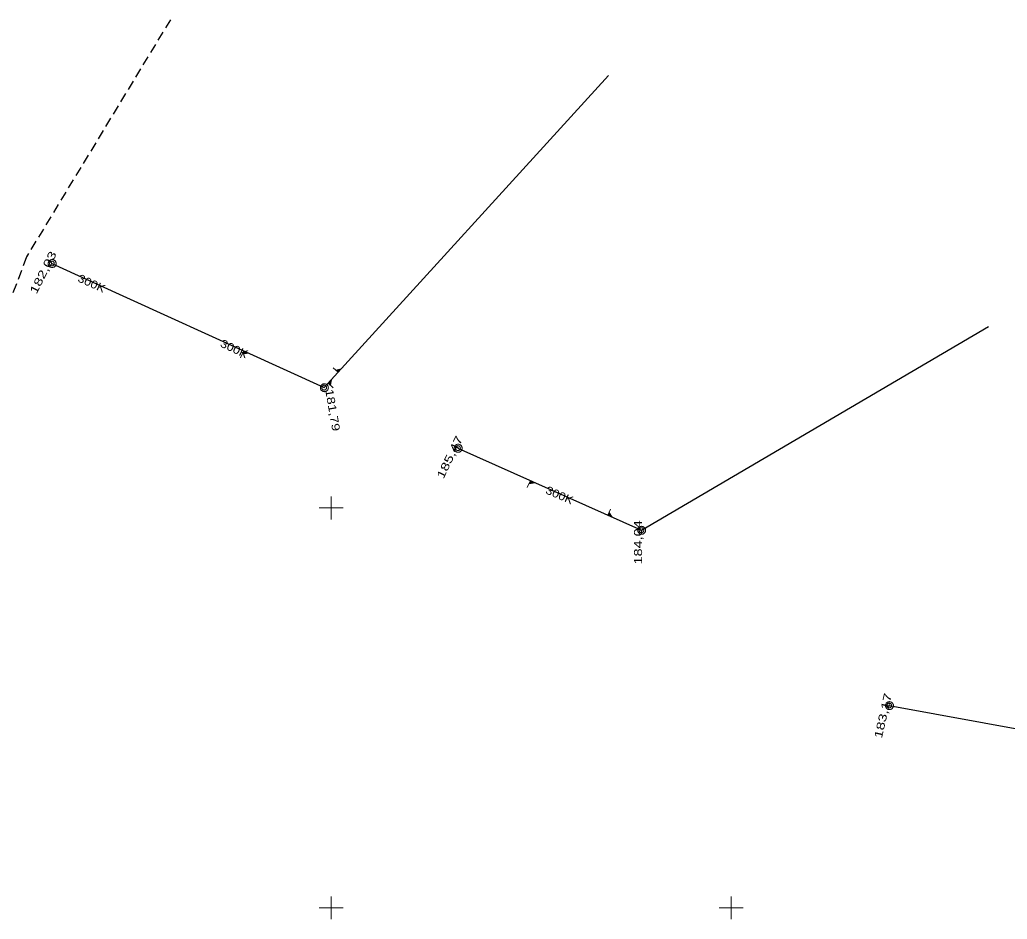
# Model space of a CAD drawing. Extents: x -740851 to -738888, y -1041382 to -1040235.
# Drawn here: x -740638.9 to -740515.5, y -1040351.4 to -1040239 of the extents above; entities that cross this region are included whole.
import ezdxf

# ---------------------------------------------------------------- set-up
doc = ezdxf.new("R2010")
doc.units = 0
doc.header["$LTSCALE"] = 0.4
doc.linetypes.add('MEDIUM_DASHED', pattern=[4.5, 3, -1.5])
for name, color, linetype, lineweight in [('1', 7, 'Continuous', 13), ('18', 7, 'Continuous', 13), ('19', 7, 'Continuous', 25), ('8', 7, 'Continuous', 13)]:
    doc.layers.add(name, color=color, linetype=linetype, lineweight=lineweight)

msp = doc.modelspace()

# ---------------------------------------------------------------- linework, layer by layer
at = {"layer": '1'}
for p, q in [((-740600, -1040298.571), (-740600, -1040301.429)), ((-740600, -1040298.571), (-740600, -1040301.429)), ((-740601.48, -1040300), (-740598.48, -1040300)), ((-740601.48, -1040300), (-740598.48, -1040300)), ((-740600, -1040348.571), (-740600, -1040351.429)), ((-740550, -1040348.571), (-740550, -1040351.429)), ((-740601.48, -1040350), (-740598.48, -1040350)), ((-740551.48, -1040350), (-740548.48, -1040350))]:
    msp.add_line(p, q, dxfattribs=at)
at = {"layer": '18'}
for points in [[(-740634.36, -1040269.45), (-740634.37, -1040269.4), (-740634.37, -1040269.35), (-740634.39, -1040269.3), (-740634.41, -1040269.25), (-740634.43, -1040269.2), (-740634.46, -1040269.16), (-740634.49, -1040269.12), (-740634.53, -1040269.08), (-740634.57, -1040269.05), (-740634.61, -1040269.02), (-740634.66, -1040269), (-740634.71, -1040268.98), (-740634.76, -1040268.96), (-740634.81, -1040268.96), (-740634.86, -1040268.95), (-740634.91, -1040268.96), (-740634.96, -1040268.96), (-740635.01, -1040268.98), (-740635.06, -1040269), (-740635.11, -1040269.02), (-740635.15, -1040269.05), (-740635.19, -1040269.08), (-740635.23, -1040269.12), (-740635.26, -1040269.16), (-740635.29, -1040269.2), (-740635.31, -1040269.25), (-740635.33, -1040269.3), (-740635.35, -1040269.35), (-740635.35, -1040269.4), (-740635.36, -1040269.45), (-740635.35, -1040269.5), (-740635.35, -1040269.55), (-740635.33, -1040269.6), (-740635.31, -1040269.65), (-740635.29, -1040269.7), (-740635.26, -1040269.74), (-740635.23, -1040269.78), (-740635.19, -1040269.82), (-740635.15, -1040269.85), (-740635.11, -1040269.88), (-740635.06, -1040269.9), (-740635.01, -1040269.92), (-740634.96, -1040269.94), (-740634.91, -1040269.94), (-740634.86, -1040269.95), (-740634.81, -1040269.94), (-740634.76, -1040269.94), (-740634.71, -1040269.92), (-740634.66, -1040269.9), (-740634.61, -1040269.88), (-740634.57, -1040269.85), (-740634.53, -1040269.82), (-740634.49, -1040269.78), (-740634.46, -1040269.74), (-740634.43, -1040269.7), (-740634.41, -1040269.65), (-740634.39, -1040269.6), (-740634.37, -1040269.55), (-740634.37, -1040269.5)], [(-740634.59, -1040269.44), (-740634.59, -1040269.41), (-740634.596, -1040269.38), (-740634.602, -1040269.35), (-740634.614, -1040269.32), (-740634.632, -1040269.29), (-740634.65, -1040269.266), (-740634.668, -1040269.242), (-740634.692, -1040269.218), (-740634.716, -1040269.2), (-740634.74, -1040269.182), (-740634.77, -1040269.164), (-740634.8, -1040269.152), (-740634.83, -1040269.146), (-740634.86, -1040269.14), (-740634.89, -1040269.14), (-740634.92, -1040269.14), (-740634.95, -1040269.146), (-740634.98, -1040269.152), (-740635.01, -1040269.164), (-740635.04, -1040269.182), (-740635.064, -1040269.2), (-740635.088, -1040269.218), (-740635.112, -1040269.242), (-740635.13, -1040269.266), (-740635.148, -1040269.29), (-740635.166, -1040269.32), (-740635.178, -1040269.35), (-740635.184, -1040269.38), (-740635.19, -1040269.41), (-740635.19, -1040269.44), (-740635.19, -1040269.47), (-740635.184, -1040269.5), (-740635.178, -1040269.53), (-740635.166, -1040269.56), (-740635.148, -1040269.59), (-740635.13, -1040269.614), (-740635.112, -1040269.638), (-740635.088, -1040269.662), (-740635.064, -1040269.68), (-740635.04, -1040269.698), (-740635.01, -1040269.716), (-740634.98, -1040269.728), (-740634.95, -1040269.734), (-740634.92, -1040269.74), (-740634.89, -1040269.74), (-740634.86, -1040269.74), (-740634.83, -1040269.734), (-740634.8, -1040269.728), (-740634.77, -1040269.716), (-740634.74, -1040269.698), (-740634.716, -1040269.68), (-740634.692, -1040269.662), (-740634.668, -1040269.638), (-740634.65, -1040269.614), (-740634.632, -1040269.59), (-740634.614, -1040269.56), (-740634.602, -1040269.53), (-740634.596, -1040269.5), (-740634.59, -1040269.47)], [(-740600.33, -1040284.97), (-740600.34, -1040284.92), (-740600.34, -1040284.87), (-740600.36, -1040284.82), (-740600.38, -1040284.77), (-740600.4, -1040284.72), (-740600.43, -1040284.68), (-740600.46, -1040284.64), (-740600.5, -1040284.6), (-740600.54, -1040284.57), (-740600.58, -1040284.54), (-740600.63, -1040284.52), (-740600.68, -1040284.5), (-740600.73, -1040284.48), (-740600.78, -1040284.48), (-740600.83, -1040284.47), (-740600.88, -1040284.48), (-740600.93, -1040284.48), (-740600.98, -1040284.5), (-740601.03, -1040284.52), (-740601.08, -1040284.54), (-740601.12, -1040284.57), (-740601.16, -1040284.6), (-740601.2, -1040284.64), (-740601.23, -1040284.68), (-740601.26, -1040284.72), (-740601.28, -1040284.77), (-740601.3, -1040284.82), (-740601.32, -1040284.87), (-740601.32, -1040284.92), (-740601.33, -1040284.97), (-740601.32, -1040285.02), (-740601.32, -1040285.07), (-740601.3, -1040285.12), (-740601.28, -1040285.17), (-740601.26, -1040285.22), (-740601.23, -1040285.26), (-740601.2, -1040285.3), (-740601.16, -1040285.34), (-740601.12, -1040285.37), (-740601.08, -1040285.4), (-740601.03, -1040285.42), (-740600.98, -1040285.44), (-740600.93, -1040285.46), (-740600.88, -1040285.46), (-740600.83, -1040285.47), (-740600.78, -1040285.46), (-740600.73, -1040285.46), (-740600.68, -1040285.44), (-740600.63, -1040285.42), (-740600.58, -1040285.4), (-740600.54, -1040285.37), (-740600.5, -1040285.34), (-740600.46, -1040285.3), (-740600.43, -1040285.26), (-740600.4, -1040285.22), (-740600.38, -1040285.17), (-740600.36, -1040285.12), (-740600.34, -1040285.07), (-740600.34, -1040285.02)], [(-740600.56, -1040284.96), (-740600.56, -1040284.93), (-740600.566, -1040284.9), (-740600.572, -1040284.87), (-740600.584, -1040284.84), (-740600.602, -1040284.81), (-740600.62, -1040284.786), (-740600.638, -1040284.762), (-740600.662, -1040284.738), (-740600.686, -1040284.72), (-740600.71, -1040284.702), (-740600.74, -1040284.684), (-740600.77, -1040284.672), (-740600.8, -1040284.666), (-740600.83, -1040284.66), (-740600.86, -1040284.66), (-740600.89, -1040284.66), (-740600.92, -1040284.666), (-740600.95, -1040284.672), (-740600.98, -1040284.684), (-740601.01, -1040284.702), (-740601.034, -1040284.72), (-740601.058, -1040284.738), (-740601.082, -1040284.762), (-740601.1, -1040284.786), (-740601.118, -1040284.81), (-740601.136, -1040284.84), (-740601.148, -1040284.87), (-740601.154, -1040284.9), (-740601.16, -1040284.93), (-740601.16, -1040284.96), (-740601.16, -1040284.99), (-740601.154, -1040285.02), (-740601.148, -1040285.05), (-740601.136, -1040285.08), (-740601.118, -1040285.11), (-740601.1, -1040285.134), (-740601.082, -1040285.158), (-740601.058, -1040285.182), (-740601.034, -1040285.2), (-740601.01, -1040285.218), (-740600.98, -1040285.236), (-740600.95, -1040285.248), (-740600.92, -1040285.254), (-740600.89, -1040285.26), (-740600.86, -1040285.26), (-740600.83, -1040285.26), (-740600.8, -1040285.254), (-740600.77, -1040285.248), (-740600.74, -1040285.236), (-740600.71, -1040285.218), (-740600.686, -1040285.2), (-740600.662, -1040285.182), (-740600.638, -1040285.158), (-740600.62, -1040285.134), (-740600.602, -1040285.11), (-740600.584, -1040285.08), (-740600.572, -1040285.05), (-740600.566, -1040285.02), (-740600.56, -1040284.99)], [(-740583.61, -1040292.54), (-740583.62, -1040292.49), (-740583.62, -1040292.44), (-740583.64, -1040292.39), (-740583.66, -1040292.34), (-740583.68, -1040292.29), (-740583.71, -1040292.25), (-740583.74, -1040292.21), (-740583.78, -1040292.17), (-740583.82, -1040292.14), (-740583.86, -1040292.11), (-740583.91, -1040292.09), (-740583.96, -1040292.07), (-740584.01, -1040292.05), (-740584.06, -1040292.05), (-740584.11, -1040292.04), (-740584.16, -1040292.05), (-740584.21, -1040292.05), (-740584.26, -1040292.07), (-740584.31, -1040292.09), (-740584.36, -1040292.11), (-740584.4, -1040292.14), (-740584.44, -1040292.17), (-740584.48, -1040292.21), (-740584.51, -1040292.25), (-740584.54, -1040292.29), (-740584.56, -1040292.34), (-740584.58, -1040292.39), (-740584.6, -1040292.44), (-740584.6, -1040292.49), (-740584.61, -1040292.54), (-740584.6, -1040292.59), (-740584.6, -1040292.64), (-740584.58, -1040292.69), (-740584.56, -1040292.74), (-740584.54, -1040292.79), (-740584.51, -1040292.83), (-740584.48, -1040292.87), (-740584.44, -1040292.91), (-740584.4, -1040292.94), (-740584.36, -1040292.97), (-740584.31, -1040292.99), (-740584.26, -1040293.01), (-740584.21, -1040293.03), (-740584.16, -1040293.03), (-740584.11, -1040293.04), (-740584.06, -1040293.03), (-740584.01, -1040293.03), (-740583.96, -1040293.01), (-740583.91, -1040292.99), (-740583.86, -1040292.97), (-740583.82, -1040292.94), (-740583.78, -1040292.91), (-740583.74, -1040292.87), (-740583.71, -1040292.83), (-740583.68, -1040292.79), (-740583.66, -1040292.74), (-740583.64, -1040292.69), (-740583.62, -1040292.64), (-740583.62, -1040292.59)], [(-740583.84, -1040292.53), (-740583.84, -1040292.5), (-740583.846, -1040292.47), (-740583.852, -1040292.44), (-740583.864, -1040292.41), (-740583.882, -1040292.38), (-740583.9, -1040292.356), (-740583.918, -1040292.332), (-740583.942, -1040292.308), (-740583.966, -1040292.29), (-740583.99, -1040292.272), (-740584.02, -1040292.254), (-740584.05, -1040292.242), (-740584.08, -1040292.236), (-740584.11, -1040292.23), (-740584.14, -1040292.23), (-740584.17, -1040292.23), (-740584.2, -1040292.236), (-740584.23, -1040292.242), (-740584.26, -1040292.254), (-740584.29, -1040292.272), (-740584.314, -1040292.29), (-740584.338, -1040292.308), (-740584.362, -1040292.332), (-740584.38, -1040292.356), (-740584.398, -1040292.38), (-740584.416, -1040292.41), (-740584.428, -1040292.44), (-740584.434, -1040292.47), (-740584.44, -1040292.5), (-740584.44, -1040292.53), (-740584.44, -1040292.56), (-740584.434, -1040292.59), (-740584.428, -1040292.62), (-740584.416, -1040292.65), (-740584.398, -1040292.68), (-740584.38, -1040292.704), (-740584.362, -1040292.728), (-740584.338, -1040292.752), (-740584.314, -1040292.77), (-740584.29, -1040292.788), (-740584.26, -1040292.806), (-740584.23, -1040292.818), (-740584.2, -1040292.824), (-740584.17, -1040292.83), (-740584.14, -1040292.83), (-740584.11, -1040292.83), (-740584.08, -1040292.824), (-740584.05, -1040292.818), (-740584.02, -1040292.806), (-740583.99, -1040292.788), (-740583.966, -1040292.77), (-740583.942, -1040292.752), (-740583.918, -1040292.728), (-740583.9, -1040292.704), (-740583.882, -1040292.68), (-740583.864, -1040292.65), (-740583.852, -1040292.62), (-740583.846, -1040292.59), (-740583.84, -1040292.56)], [(-740560.68, -1040302.8), (-740560.69, -1040302.75), (-740560.69, -1040302.7), (-740560.71, -1040302.65), (-740560.73, -1040302.6), (-740560.75, -1040302.55), (-740560.78, -1040302.51), (-740560.81, -1040302.47), (-740560.85, -1040302.43), (-740560.89, -1040302.4), (-740560.93, -1040302.37), (-740560.98, -1040302.35), (-740561.03, -1040302.33), (-740561.08, -1040302.31), (-740561.13, -1040302.31), (-740561.18, -1040302.3), (-740561.23, -1040302.31), (-740561.28, -1040302.31), (-740561.33, -1040302.33), (-740561.38, -1040302.35), (-740561.43, -1040302.37), (-740561.47, -1040302.4), (-740561.51, -1040302.43), (-740561.55, -1040302.47), (-740561.58, -1040302.51), (-740561.61, -1040302.55), (-740561.63, -1040302.6), (-740561.65, -1040302.65), (-740561.67, -1040302.7), (-740561.67, -1040302.75), (-740561.68, -1040302.8), (-740561.67, -1040302.85), (-740561.67, -1040302.9), (-740561.65, -1040302.95), (-740561.63, -1040303), (-740561.61, -1040303.05), (-740561.58, -1040303.09), (-740561.55, -1040303.13), (-740561.51, -1040303.17), (-740561.47, -1040303.2), (-740561.43, -1040303.23), (-740561.38, -1040303.25), (-740561.33, -1040303.27), (-740561.28, -1040303.29), (-740561.23, -1040303.29), (-740561.18, -1040303.3), (-740561.13, -1040303.29), (-740561.08, -1040303.29), (-740561.03, -1040303.27), (-740560.98, -1040303.25), (-740560.93, -1040303.23), (-740560.89, -1040303.2), (-740560.85, -1040303.17), (-740560.81, -1040303.13), (-740560.78, -1040303.09), (-740560.75, -1040303.05), (-740560.73, -1040303), (-740560.71, -1040302.95), (-740560.69, -1040302.9), (-740560.69, -1040302.85)], [(-740560.91, -1040302.79), (-740560.91, -1040302.76), (-740560.916, -1040302.73), (-740560.922, -1040302.7), (-740560.934, -1040302.67), (-740560.952, -1040302.64), (-740560.97, -1040302.616), (-740560.988, -1040302.592), (-740561.012, -1040302.568), (-740561.036, -1040302.55), (-740561.06, -1040302.532), (-740561.09, -1040302.514), (-740561.12, -1040302.502), (-740561.15, -1040302.496), (-740561.18, -1040302.49), (-740561.21, -1040302.49), (-740561.24, -1040302.49), (-740561.27, -1040302.496), (-740561.3, -1040302.502), (-740561.33, -1040302.514), (-740561.36, -1040302.532), (-740561.384, -1040302.55), (-740561.408, -1040302.568), (-740561.432, -1040302.592), (-740561.45, -1040302.616), (-740561.468, -1040302.64), (-740561.486, -1040302.67), (-740561.498, -1040302.7), (-740561.504, -1040302.73), (-740561.51, -1040302.76), (-740561.51, -1040302.79), (-740561.51, -1040302.82), (-740561.504, -1040302.85), (-740561.498, -1040302.88), (-740561.486, -1040302.91), (-740561.468, -1040302.94), (-740561.45, -1040302.964), (-740561.432, -1040302.988), (-740561.408, -1040303.012), (-740561.384, -1040303.03), (-740561.36, -1040303.048), (-740561.33, -1040303.066), (-740561.3, -1040303.078), (-740561.27, -1040303.084), (-740561.24, -1040303.09), (-740561.21, -1040303.09), (-740561.18, -1040303.09), (-740561.15, -1040303.084), (-740561.12, -1040303.078), (-740561.09, -1040303.066), (-740561.06, -1040303.048), (-740561.036, -1040303.03), (-740561.012, -1040303.012), (-740560.988, -1040302.988), (-740560.97, -1040302.964), (-740560.952, -1040302.94), (-740560.934, -1040302.91), (-740560.922, -1040302.88), (-740560.916, -1040302.85), (-740560.91, -1040302.82)], [(-740529.71, -1040324.72), (-740529.72, -1040324.67), (-740529.72, -1040324.62), (-740529.74, -1040324.57), (-740529.76, -1040324.52), (-740529.78, -1040324.47), (-740529.81, -1040324.43), (-740529.84, -1040324.39), (-740529.88, -1040324.35), (-740529.92, -1040324.32), (-740529.96, -1040324.29), (-740530.01, -1040324.27), (-740530.06, -1040324.25), (-740530.11, -1040324.23), (-740530.16, -1040324.23), (-740530.21, -1040324.22), (-740530.26, -1040324.23), (-740530.31, -1040324.23), (-740530.36, -1040324.25), (-740530.41, -1040324.27), (-740530.46, -1040324.29), (-740530.5, -1040324.32), (-740530.54, -1040324.35), (-740530.58, -1040324.39), (-740530.61, -1040324.43), (-740530.64, -1040324.47), (-740530.66, -1040324.52), (-740530.68, -1040324.57), (-740530.7, -1040324.62), (-740530.7, -1040324.67), (-740530.71, -1040324.72), (-740530.7, -1040324.77), (-740530.7, -1040324.82), (-740530.68, -1040324.87), (-740530.66, -1040324.92), (-740530.64, -1040324.97), (-740530.61, -1040325.01), (-740530.58, -1040325.05), (-740530.54, -1040325.09), (-740530.5, -1040325.12), (-740530.46, -1040325.15), (-740530.41, -1040325.17), (-740530.36, -1040325.19), (-740530.31, -1040325.21), (-740530.26, -1040325.21), (-740530.21, -1040325.22), (-740530.16, -1040325.21), (-740530.11, -1040325.21), (-740530.06, -1040325.19), (-740530.01, -1040325.17), (-740529.96, -1040325.15), (-740529.92, -1040325.12), (-740529.88, -1040325.09), (-740529.84, -1040325.05), (-740529.81, -1040325.01), (-740529.78, -1040324.97), (-740529.76, -1040324.92), (-740529.74, -1040324.87), (-740529.72, -1040324.82), (-740529.72, -1040324.77)], [(-740529.94, -1040324.71), (-740529.94, -1040324.68), (-740529.946, -1040324.65), (-740529.952, -1040324.62), (-740529.964, -1040324.59), (-740529.982, -1040324.56), (-740530, -1040324.536), (-740530.018, -1040324.512), (-740530.042, -1040324.488), (-740530.066, -1040324.47), (-740530.09, -1040324.452), (-740530.12, -1040324.434), (-740530.15, -1040324.422), (-740530.18, -1040324.416), (-740530.21, -1040324.41), (-740530.24, -1040324.41), (-740530.27, -1040324.41), (-740530.3, -1040324.416), (-740530.33, -1040324.422), (-740530.36, -1040324.434), (-740530.39, -1040324.452), (-740530.414, -1040324.47), (-740530.438, -1040324.488), (-740530.462, -1040324.512), (-740530.48, -1040324.536), (-740530.498, -1040324.56), (-740530.516, -1040324.59), (-740530.528, -1040324.62), (-740530.534, -1040324.65), (-740530.54, -1040324.68), (-740530.54, -1040324.71), (-740530.54, -1040324.74), (-740530.534, -1040324.77), (-740530.528, -1040324.8), (-740530.516, -1040324.83), (-740530.498, -1040324.86), (-740530.48, -1040324.884), (-740530.462, -1040324.908), (-740530.438, -1040324.932), (-740530.414, -1040324.95), (-740530.39, -1040324.968), (-740530.36, -1040324.986), (-740530.33, -1040324.998), (-740530.3, -1040325.004), (-740530.27, -1040325.01), (-740530.24, -1040325.01), (-740530.21, -1040325.01), (-740530.18, -1040325.004), (-740530.15, -1040324.998), (-740530.12, -1040324.986), (-740530.09, -1040324.968), (-740530.066, -1040324.95), (-740530.042, -1040324.932), (-740530.018, -1040324.908), (-740530, -1040324.884), (-740529.982, -1040324.86), (-740529.964, -1040324.83), (-740529.952, -1040324.8), (-740529.946, -1040324.77), (-740529.94, -1040324.74)]]:
    msp.add_lwpolyline(points, close=True, dxfattribs=at)
for points in [[(-740611.303, -1040281.232), (-740610.913, -1040280.377), (-740610.303, -1040280.656), (-740611.089, -1040280.763)], [(-740611.005, -1040280.698), (-740610.892, -1040280.449), (-740610.502, -1040280.627), (-740611.009, -1040280.696)], [(-740610.919, -1040280.629), (-740610.862, -1040280.504), (-740610.663, -1040280.595), (-740610.923, -1040280.627)], [(-740599.716, -1040282.486), (-740599.109, -1040283.038), (-740598.716, -1040282.605), (-740599.383, -1040282.789)], [(-740599.293, -1040282.812), (-740599.117, -1040282.973), (-740598.865, -1040282.697), (-740599.296, -1040282.815)], [(-740599.2, -1040282.838), (-740599.112, -1040282.919), (-740598.983, -1040282.777), (-740599.203, -1040282.841)], [(-740599.737, -1040284.966), (-740600.352, -1040284.405), (-740599.952, -1040283.966), (-740600.074, -1040284.658)], [(-740600.107, -1040284.57), (-740600.286, -1040284.406), (-740600.03, -1040284.126), (-740600.109, -1040284.573)], [(-740600.142, -1040284.479), (-740600.232, -1040284.397), (-740600.1, -1040284.253), (-740600.145, -1040284.481)], [(-740575.469, -1040297.446), (-740575.084, -1040296.585), (-740574.469, -1040296.86), (-740575.257, -1040296.973)], [(-740575.174, -1040296.907), (-740575.061, -1040296.656), (-740574.669, -1040296.832), (-740575.178, -1040296.905)], [(-740575.088, -1040296.837), (-740575.032, -1040296.711), (-740574.83, -1040296.802), (-740575.092, -1040296.835)], [(-740565.07, -1040300.153), (-740565.409, -1040300.911), (-740564.868, -1040301.153), (-740565.256, -1040300.569)], [(-740565.25, -1040300.663), (-740565.349, -1040300.884), (-740565.003, -1040301.038), (-740565.254, -1040300.661)], [(-740565.246, -1040300.76), (-740565.295, -1040300.871), (-740565.118, -1040300.95), (-740565.25, -1040300.759)]]:
    msp.add_lwpolyline(points, dxfattribs=at)
at = {"layer": '19'}
for p, q in [((-740600.86, -1040284.96), (-740565.31, -1040245.92)), ((-740634.89, -1040269.44), (-740600.86, -1040284.96)), ((-740561.21, -1040302.79), (-740517.81, -1040277.3)), ((-740584.14, -1040292.53), (-740561.21, -1040302.79)), ((-740530.24, -1040324.71), (-740472.33, -1040335.26))]:
    msp.add_line(p, q, dxfattribs=at)
at = {"layer": '8', "linetype": 'MEDIUM_DASHED', "lineweight": 25}
msp.add_lwpolyline([(-740620.084, -1040238.965), (-740638.07, -1040268.62), (-740646.59, -1040291.365)], dxfattribs=at)

# ---------------------------------------------------------------- texts
at = {"layer": '18'}
for s, rotation, width, p in [('182,03', 63.332, 1.4, (-740636.823, -1040273.342)), ('300K', 335.801, 1.15, (-740631.758, -1040271.648)), ('300K', 335.108, 1.15, (-740613.942, -1040279.794)), ('181,79', 279.84, 1.3, (-740600.737, -1040285.235)), ('185,47', 64.278, 1.4, (-740585.96, -1040296.451)), ('300K', 336.488, 1.15, (-740573.278, -1040298.15)), ('184,04', 90.219, 1.35, (-740561.123, -1040307.071)), ('183,17', 77.076, 1.4, (-740531.165, -1040328.885))]:
    msp.add_text(s, height=1, rotation=rotation, dxfattribs=dict(at, width=width)).set_placement(p)

doc.saveas('drawing.dxf')
